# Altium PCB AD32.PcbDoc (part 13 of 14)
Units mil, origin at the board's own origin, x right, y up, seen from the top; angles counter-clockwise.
Board outline 7007.87 x 4368.85 mil, 12 copper layers (Top Layer, Int1 (GND), Int2 (AVDD), Int3 (DVDD), Int4 (GND), Int5 (ST), Int6 (SB), Int8 (AGND), Int7 (AVCC), Int9 (VCCA), Int10 (GND), Bottom Layer), stack 60.136 mil thick; 1350 components, 880 nets, 4712 pads, 2835 vias.
Unrouted connection lines stored in the file: 19.
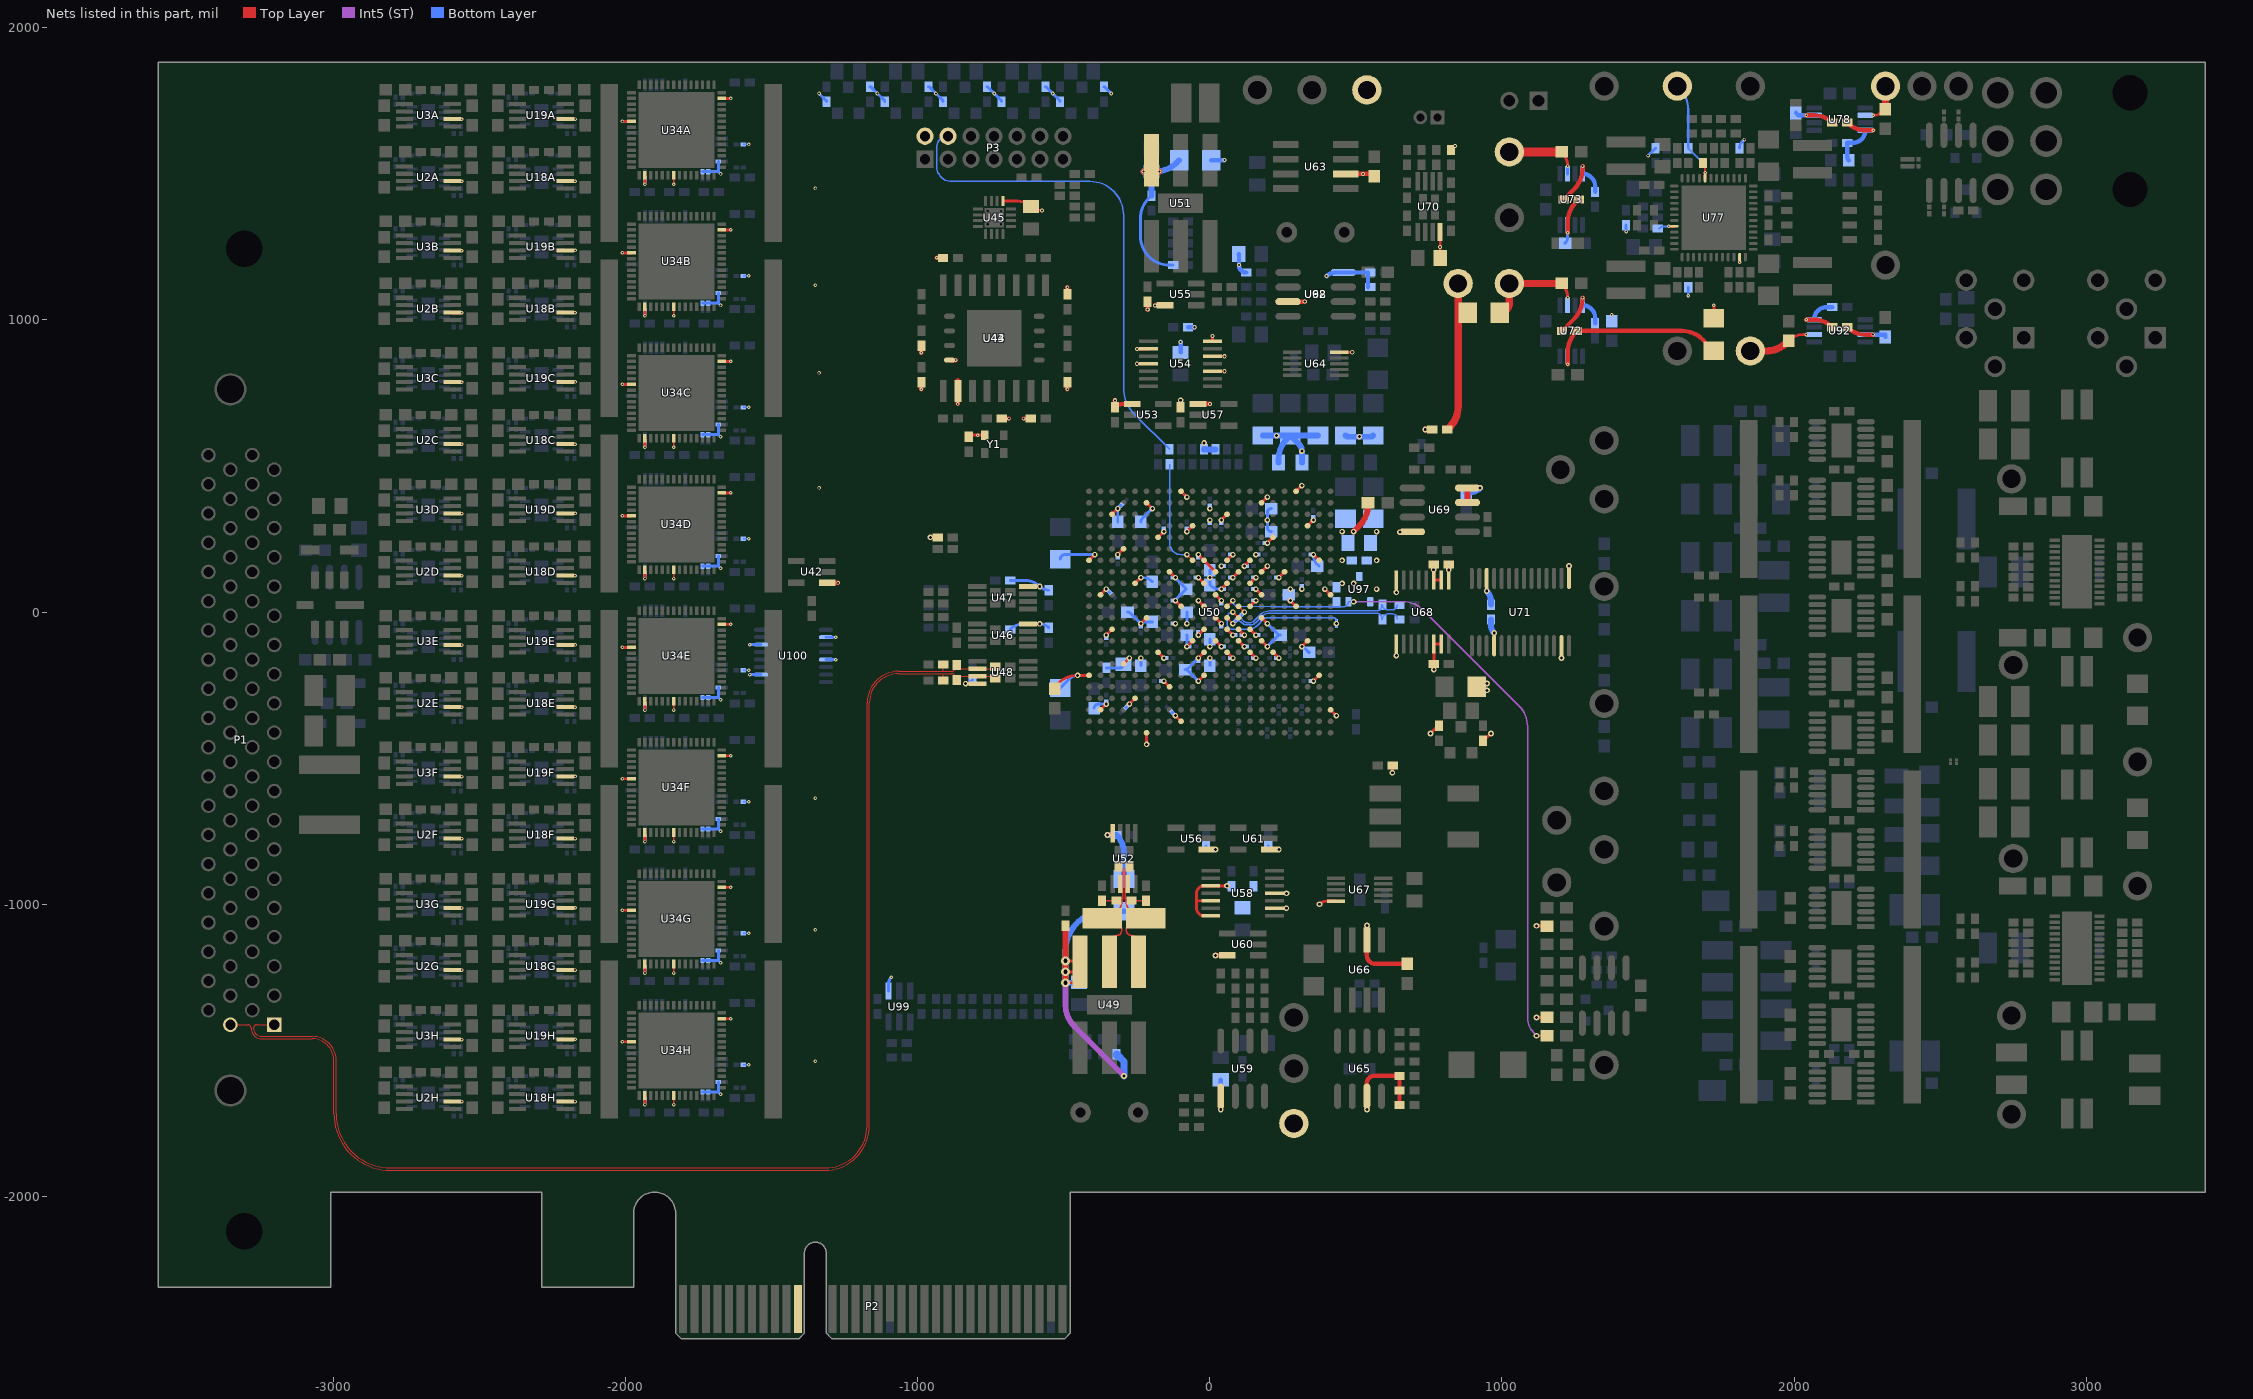
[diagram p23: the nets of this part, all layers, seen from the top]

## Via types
v1: diameter 12, hole 6, Top Layer to Bottom Layer, tented both sides, 1497 vias
v2: diameter 20, hole 10, Top Layer to Bottom Layer, tented both sides, 364 vias
v3: diameter 19, hole 10, Top Layer to Bottom Layer, tented both sides, 347 vias
v4: diameter 14, hole 7, Top Layer to Bottom Layer, tented both sides, 228 vias
v5: diameter 19.68, hole 7.87, Top Layer to Bottom Layer, 225 vias
v6: diameter 19.02, hole 10, Top Layer to Bottom Layer, tented both sides, 85 vias
v7: diameter 20, hole 10, Top Layer to Bottom Layer, 32 vias
v8: diameter 40, hole 20, Top Layer to Bottom Layer, tented both sides, 14 vias
v9: diameter 30, hole 15, Top Layer to Bottom Layer, tented both sides, 12 vias
v10: diameter 25, hole 13, Top Layer to Bottom Layer, 8 vias
v11: diameter 40, hole 20, Top Layer to Bottom Layer, 6 vias
v12: diameter 50, hole 20, Top Layer to Bottom Layer, 6 vias
v13: diameter 66, hole 47, Top Layer to Bottom Layer, tented both sides, 3 vias
v14: diameter 63, hole 45, Top Layer to Bottom Layer, 2 vias
v15: diameter 50, hole 25, Top Layer to Bottom Layer, 2 vias
v16: diameter 12, hole 6, Top Layer to Bottom Layer, 2 vias
v17: diameter 60, hole 40, Top Layer to Bottom Layer, tented both sides, 1 vias
v18: diameter 60, hole 40, Top Layer to Bottom Layer, 1 vias

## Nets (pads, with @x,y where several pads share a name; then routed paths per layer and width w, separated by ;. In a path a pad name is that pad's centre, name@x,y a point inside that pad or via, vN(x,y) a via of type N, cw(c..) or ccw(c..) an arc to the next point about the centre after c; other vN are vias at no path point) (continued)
TMS_FPGA: R374.2 U50.T13 | length 379.1
  Top Layer w5: v3(-78.74,196.85) U50.T13@-59.05,177.17
  Bottom Layer w5: R374.2@-137.8,505.91 -137.8,236.12 ccw(c-98.53,236.12) -98.53,196.85 v3(-78.74,196.85)
TMS_JTAG: P3.4 R374.1 | length 1721.3
  Bottom Layer w5: P3.4@-896.26,1628.74 ccw(c-896.26,1590.04) -934.96,1590.04 -934.96,1550 -935.02,1525.62 ccw(c-883.51,1525.62) -883.51,1474.11 -411.02,1474.11 cw(c-411.02,1358.36) -295.28,1358.36 -295.28,769.03 ccw(c-163.78,769.03) -256.76,676.05 R374.1@-137.8,557.09
TRG_N: P1.2 R137.2 R143.1 R148.2 U48.7 | length 4617.4
  Top Layer w4: P1.2@-3352.3,-1412.5 -3293.31,-1412.5 cw(c-3293.31,-1424.5) -3281.3,-1424.5 ccw(c-3245.68,-1424.5) -3245.68,-1460.12 -3072.5,-1460.12 cw(c-3072.5,-1534.62) -2998,-1534.62 -2998,-1717.62 ccw(c-2805.12,-1717.62) -2805.12,-1910.5 -1317.5,-1910.5 ccw(c-1317.5,-1758) -1165,-1758 -1165,-310.69 cw(c-1065,-310.69) -1065,-210.69 -911.91,-210.69 ; R137.2@-911.91,-233.9 -911.91,-210.69 ; R143.1@-873.13,-219.49 U48.7@-795.08,-219.49 -750.89,-219.49 cw(c-750.89,-243.01) R148.2@-734.25,-226.38 ; R143.1@-866.14,-232.28 cw(c-860.11,-226.25) -868.64,-226.25 ccw(c-884.2,-226.25) -870.19,-219.49 ccw(c-884.2,-226.25) -884.2,-210.69 -911.91,-210.69
TRG_P: P1.1 R136.1 R143.2 R149.2 U48.6 | length 4609.6
  Top Layer w4: P1.1@-3202.3,-1412.5 -3261.3,-1412.5 ccw(c-3261.3,-1424.5) -3273.3,-1424.5 ccw(c-3245.68,-1424.5) -3245.68,-1452.12 -3072.5,-1452.12 cw(c-3072.5,-1534.62) -2990,-1534.62 -2990,-1717.62 ccw(c-2805.12,-1717.62) -2805.12,-1902.5 -1317.5,-1902.5 ccw(c-1317.5,-1758) -1173,-1758 -1173,-310.69 cw(c-1065,-310.69) -1065,-202.69 -911.91,-202.69 ; R136.1@-911.91,-178.9 -911.91,-202.69 ; R143.2@-877.26,-193.9 U48.6@-795.08,-193.9 -750.89,-193.9 ccw(c-750.89,-170.37) R149.2@-734.25,-187.01 ; R143.2@-866.14,-181.1 ccw(c-860.11,-187.14) -868.64,-187.14 cw(c-884.2,-187.14) -870.19,-193.9 cw(c-884.2,-187.14) -884.2,-202.69 -911.91,-202.69
VCC: C40.2 C41.2 C42.2 C55.2 C116.1 C117.1 C143.1 C187.2 C201.2 C203.1 C216.2 C229.2 C236.2 C241.1 C256.2 C274.2 C275.2 C282.2 FR3.1 FR11.2 FR12.2 R194.1 R197.1 R209.1 R210.1 R240.1 R267.1 R345.2 R385.1 R387.1 TP10.1 U46.8 U47.8 U48.8 U52.8 U53.1 U54.2 U54.4 U54.10 U54.12 U54.14 U55.5 U56.1 U57.1 U58.2 U58.4 U58.10 U58.12 U58.14 U60.5 U61.1 U70.8 U72.2 U73.7 U78.7 U92.7 | length 2687.5
  Top Layer w8: C55.2@783.46,1218.75 ccw(c783.46,1223.67) 788.39,1223.67 U70.8@788.39,1301.08
  Top Layer w9.92: U58.14@3.25,-1039.27 -19.72,-1039.27 cw(c-19.72,-1013.68) -45.31,-1013.68 -45.31,-988.09 ; U58.12@3.25,-988.09 -45.31,-988.09 ; v2(58.78,-936.91) U58.10@3.25,-936.91 -19.72,-936.91 ccw(c-19.72,-962.5) -45.31,-962.5 -45.31,-988.09
  Top Layer w10: v3(-835.96,-245.08) U48.8@-795.08,-245.08 ; U46.8@-622.24,-40.35 v3(-582.07,-40.35) ; U47.8@-622.24,87.6 v3(-582.07,87.6) ; v4(-249.61,850) U54.4@-209.25,850 ; v4(-249.61,901.18) U54.2@-209.25,901.18 ; U56.1@-9.35,-812.4 -9.25,-812.5 v2(19.69,-812.5) ; U54.10@9.25,824.41 v4(50,824.41) ; U54.12@9.25,875.59 v4(50,875.59) ; U54.14@9.25,926.77 v4(9.25,945.37) ; U61.1@203.15,-812.4 203.25,-812.5 v2(236.22,-812.5) ; U58.2@221.75,-1013.68 221.85,-1013.78 v2(261.81,-1013.78) ; U58.4@221.75,-962.5 v2(261.91,-962.5) ; R194.1@825,1581.84 838.66,1595.5 v4(838.66,1595.58) ; R210.1@1204.04,1125 1205.15,1123.89 cw(c1157.93,1076.67) v1(1224.7,1076.67)
  Top Layer w15: v2(-350,-762.5) -337.3,-762.5 ccw(c-337.3,-757.33) U52.8@-332.14,-757.33 ; v4(-325,725) C40.2@-325,700.59 cw(c-296.49,672.08) -296.49,712.4 U53.1@-265.65,712.4 U53.1@-265.55,712.5 ; v4(-212.5,1035) C41.2@-212.5,1061.91 ; v4(-187.5,1050) -153.15,1050 U55.5@-153.15,1050.1 ; C42.2@-100,700.59 v6(-100,725) ; U57.1@-40.65,712.4 -40.55,712.5 v4(0,712.5) ; v2(19.69,-1174.9) U60.5@59.35,-1174.9 ; v1(1224.7,1298.33) 1224.7,1332.69 cw(c1324.7,1332.69) 1253.99,1403.4 C143.1@1263.09,1412.5 ; v1(2042.08,1700.3) 2069.59,1700.3 cw(c2069.59,1613.93) C117.1@2130.66,1675 ; C116.1@2181.84,975 ccw(c2242.91,1036.07) 2242.91,949.7 v1(2270.15,949.7)
  Top Layer w25: FR3.1@992.62,1025 ccw(c992.62,1057.38) 1025,1057.38 TP10.1@1025,1125 R210.1@1204.04,1125
  Bottom Layer w9.92: v3(-582.07,87.6) ccw(c-551.18,118.49) C274.2@-551.18,74.8
  Bottom Layer w10: v3(-835.96,-245.08) ccw(c-835.96,-220.04) -818.26,-237.75 C282.2@-812.5,-231.99 ; R385.1@-683.07,-59.06 cw(c-637.92,-104.2) -637.92,-40.35 v3(-582.07,-40.35) cw(c-582.07,-84.04) C275.2@-551.18,-53.15 ; R387.1@-683.07,108.27 -631.97,108.27 cw(c-631.97,37.7) v3(-582.07,87.6) ; C229.2@-12.5,-800.59 ccw(c-0.59,-800.59) -0.59,-812.5 v2(19.69,-812.5) ; C187.2@200,-800.59 ccw(c211.91,-800.59) 211.91,-812.5 v2(236.22,-812.5) ; R209.1@1214.84,1264.19 R209.1@1216.54,1262.5 ccw(c1196.81,1282.22) 1224.7,1282.22 v1(1224.7,1298.33) U73.7@1224.7,1324.9 ; v1(1425,1302.5) R345.2@1425,1324.41
  Bottom Layer w15: C241.1@-100,888.39 v4(-100,925) ; C236.2@-74.41,975 v4(-52.1,975) ; FR11.2@5.12,1546.74 v4(50,1546.74) ; R240.1@2006.25,1708.46 2014.42,1700.3 v1(2042.08,1700.3) U78.7@2068.65,1700.3 ; U92.7@2243.57,949.7 2312.5,949.7 R267.1@2312.5,941.54
  Bottom Layer w20: v2(-350,-762.5) C256.2@-319.34,-762.5 cw(c-381.12,-824.28) -293.75,-824.28 FR12.2@-293.75,-913.63
  other v1: 1375,1017.62
  other v4: 788.39,1250
VCC1V0: C153.2 C160.2 C171.2 C182.2 C183.2 C189.1 C194.1 C195.1 C196.1 C197.1 C198.1 C199.1 C210.1 C211.1 C212.2 C213.2 C214.1 C215.1 C218.1 C219.1 C225.2 C226.2 C227.2 R243.1 R344.2 TP28.1 U50.H8 U50.H10 U50.J7 U50.J9 U50.J11 U50.K8 U50.L7 U50.L11 U50.M8 U50.N7 U50.N11 U50.P8 U50.P10 U50.R7 U50.R9 U50.T8 U50.T10 U92.2 | length 1144.4
  Top Layer w10: U50.J11@19.69,-98.43 v3(39.37,-118.11) ; U50.L11@19.69,-19.68 v3(39.37,-39.37) ; U50.N11@19.69,59.06 v3(39.37,39.37) ; v3(39.37,78.74) U50.P10@59.06,98.43 ; U50.H10@59.06,-137.8 v3(78.74,-157.48) ; U50.T10@59.06,177.17 v3(78.74,196.85) ; v3(78.74,118.11) U50.R9@98.43,137.8 ; U50.J9@98.43,-98.43 v3(118.11,-118.11) ; v3(118.11,157.48) U50.T8@137.8,177.17 ; U50.H8@137.8,-137.8 v3(157.48,-157.48) ; U50.K8@137.8,-59.06 v3(157.48,-78.74) ; U50.M8@137.8,19.69 v3(157.48,39.37) ; U50.P8@137.8,98.43 v3(157.48,118.11) ; v3(157.48,78.74) U50.N7@177.17,59.06 ; U50.J7@177.17,-98.43 v3(196.85,-118.11) ; U50.L7@177.17,-19.68 v3(196.85,-39.37) ; U50.R7@177.17,137.8 v3(196.85,157.48) ; R243.1@1981.25,929.04 cw(c2031.15,879.14) 2031.15,949.7 v1(2041.8,949.7)
  Top Layer w25: TP28.1@1850,893.75 1904.54,893.75 ccw(c1904.54,993.75) 1975.25,923.04 R243.1@1981.25,929.04
  Bottom Layer w10: v3(0,-118.11) C225.2@0,-92.52 ; C227.2@0,143.7 v3(0,118.11) C226.2@0,92.52 ccw(c33.26,125.78) 33.26,78.74 v3(39.37,78.74) ; v3(196.85,-118.11) C171.2@236.22,-78.74 ; v3(196.85,-39.37) C171.2@236.22,-78.74 ; C182.2@210.63,275.59 cw(c210.63,289.37) 196.85,289.37 v3(196.85,314.96) 196.85,340.55 cw(c210.63,340.55) C183.2@210.63,354.33 ; C171.2@242.13,-78.74 C171.2@236.22,-78.74 ; v1(1500,1562.5) R344.2@1525,1587.5
  Bottom Layer w20: C160.2@464.57,604.33 ccw(c474.07,613.84) 474.07,600.39 v3(511.81,600.39) 549.55,600.39 ccw(c549.55,613.84) C153.2@559.06,604.33
  other v3: 39.37,157.48
VCC1V8: C37.2 C165.1 C166.2 C174.2 C177.1 C185.2 C220.2 C222.2 C223.2 C224.2 C230.2 C231.2 C232.2 C233.2 C234.2 C235.2 C237.2 C238.2 C239.2 C240.2 C243.2 C244.2 C245.2 C246.2 C247.2 C249.2 C250.2 C251.2 C252.2 C253.2 C254.2 C255.2 C257.2 C259.2 C260.2 C261.2 C262.1 C263.2 C265.2 C266.2 C267.2 C268.2 C269.1 C270.2 C271.2 C272.2 C360A.1 C360B.1 C360C.1 C360D.1 C360E.1 C360F.1 C360G.1 C360H.1 P3.2 R133.2 R134.2 R140.2 R142.1 R145.1 R146.2 R155.1 R158.2 R160.2 R191.2 R260.1 R337.2 R367.2 R369.2 R379.2 R402A.1 R402B.1 R402C.1 R402D.1 R402E.1 R402F.1 R402G.1 R402H.1 R417A.2 R417B.2 R417C.2 R417D.2 R417E.2 R417F.2 R417G.2 R417H.2 R457A.2 R457B.2 R457C.2 R457D.2 R457E.2 R457F.2 R457G.2 R457H.2 R473A.2 R473B.2 R473C.2 R473D.2 R473E.2 R473F.2 R473G.2 R473H.2 TP30.1 U34A.13 U34A.44 U34A.49 U34B.13 U34B.44 U34B.49 U34C.13 U34C.44 U34C.49 U34D.13 U34D.44 U34D.49 U34E.13 U34E.44 U34E.49 U34F.13 U34F.44 U34F.49 U34G.13 U34G.44 U34G.49 U34H.13 U34H.44 U34H.49 U43.2 U44.8 U45.5 U50.A17 U50.AA17 U50.AB14 U50.B14 U50.C21 U50.D18 U50.E15 U50.F12 U50.F22 U50.G19 U50.H12 U50.H16 U50.J13 U50.K12 U50.K20 U50.L17 U50.M12 U50.M14 U50.N21 U50.P12 U50.P18 U50.R11 U50.R15 U50.T12 U50.T22 U50.U19 U50.V16 U50.W13 U50.Y10 U50.Y20 U67.10 U78.2 U99.1 U100.2 U100.5 U100.10 U100.14 Y1.4 | length 5255.7
  Top Layer w5: v1(-1834.84,-1685.43) U34H.49@-1834.84,-1654.62 ; v1(-1834.84,-1235.43) U34G.49@-1834.84,-1204.62 ; v1(-1834.84,-785.43) U34F.49@-1834.84,-754.62 ; v1(-1834.84,-335.43) U34E.49@-1834.84,-304.62 ; v1(-1834.84,114.57) U34D.49@-1834.84,145.38 ; v1(-1834.84,564.57) U34C.49@-1834.84,595.38 ; v1(-1834.84,1014.57) U34B.49@-1834.84,1045.38 ; v1(-1834.84,1464.57) U34A.49@-1834.84,1495.38
  Top Layer w9.65: v3(-354.33,-78.74) U50.K20@-334.65,-59.06
  Top Layer w10: v1(-1933.27,-1685.43) U34H.44@-1933.27,-1654.62 ; v1(-1933.27,-1235.43) U34G.44@-1933.27,-1204.62 ; v1(-1933.27,-785.43) U34F.44@-1933.27,-754.62 ; v1(-1933.27,-335.43) U34E.44@-1933.27,-304.62 ; v1(-1933.27,114.57) U34D.44@-1933.27,145.38 ; v1(-1933.27,564.57) U34C.44@-1933.27,595.38 ; v1(-1933.27,1014.57) U34B.44@-1933.27,1045.38 ; v1(-1933.27,1464.57) U34A.44@-1933.27,1495.38 ; U34H.13@-1670.38,-1391.73 v1(-1639.57,-1391.73) ; U34G.13@-1670.38,-941.73 v1(-1639.57,-941.73) ; U34F.13@-1670.38,-491.73 v1(-1639.57,-491.73) ; U34E.13@-1670.38,-41.73 v1(-1639.57,-41.73) ; U34D.13@-1670.38,408.27 v1(-1639.57,408.27) ; U34C.13@-1670.38,858.27 v1(-1639.57,858.27) ; U34B.13@-1670.38,1308.27 v1(-1639.57,1308.27) ; U34A.13@-1670.38,1758.27 v1(-1639.57,1758.27) ; v3(-956.69,255.91) R140.2@-931.1,255.91 ; R145.1@-825,600.59 cw(c-813.12,588.71) -813.12,605.51 v1(-794.18,605.51) Y1.4@-769.98,605.51 ; U45.5@-707.97,1406.5 -656.22,1406.5 cw(c-656.22,1344.66) C37.2@-612.5,1388.39 ccw(c-580.18,1420.7) -580.18,1375 v4(-575,1375) ; C249.2@-531.5,-255.91 -519.96,-244.37 cw(c-452.76,-311.58) v3(-452.76,-216.54) U50.F22@-413.39,-216.54 ; U50.T22@-413.39,177.17 v3(-393.7,196.85) ; U50.C21@-374.02,-334.65 v3(-354.33,-314.96) ; U50.N21@-374.02,59.06 v3(-354.33,78.74) ; U50.Y20@-334.65,334.65 v3(-314.96,354.33) ; v3(-314.96,196.85) U50.U19@-295.28,216.54 ; U50.G19@-295.28,-177.17 v3(-275.59,-157.48) ; v3(-275.59,-314.96) U50.D18@-255.91,-295.28 ; U50.P18@-255.91,98.43 v3(-236.22,118.11) ; v3(-236.22,-39.37) U50.L17@-216.54,-19.68 ; v3(-216.54,-452.76) U50.A17@-216.54,-413.39 ; U50.AA17@-216.54,374.02 v3(-196.85,354.33) ; U50.H16@-177.17,-137.8 v3(-157.48,-157.48) ; U50.V16@-177.17,255.91 v3(-157.48,275.59) ; v3(-157.48,-236.22) U50.E15@-137.8,-255.91 ; U50.R15@-137.8,137.8 v3(-118.11,118.11) ; v3(-118.11,-354.33) U50.B14@-98.43,-374.02 ; v3(-118.11,39.37) U50.M14@-98.43,19.69 ; U50.AB14@-98.43,413.39 v3(-78.74,393.7) ; v3(-78.74,-118.11) U50.J13@-59.05,-98.43 ; v3(-78.74,275.59) U50.W13@-59.05,295.28 ; v3(-39.37,-236.22) U50.F12@-19.68,-216.54 ; v3(-39.37,-157.48) U50.H12@-19.68,-137.8 ; v3@-39.37,-78.74 U50.K12@-19.68,-59.06 ; v3(-39.37,39.37) U50.M12@-19.68,19.69 ; v3(-39.37,118.11) U50.P12@-19.68,98.43 ; v3(-39.37,196.85) U50.T12@-19.68,177.17 U50.R11@19.69,137.8 ; v3(39.37,314.96) U50.Y10@59.06,334.65 ; v2(375,-1000) cw(c400.66,-1025.66) 400.66,-989.37 U67.10@431.79,-989.37 ; v3(625,-550) 625,-525.59 R379.2@625.59,-525 ; v2(755,-415) 777.47,-392.53 cw(c785,-400.05) R191.2@785,-389.41 ; v1(2270.42,1700.3) ccw(c2270.42,1751.98) 2306.97,1715.43 R260.1@2312.5,1720.96
  Top Layer w15: v1@-987.5,763.09 R133.2@-987.5,786.91 ; v1(-987.5,887.5) R134.2@-987.5,911.91 ; v1(-934.96,1212.5) R142.1@-913.09,1212.5 ; U44.8@-891.04,862.5 v1(-869.9,862.5) ; v1(-862.5,712.5) U43.2@-862.5,756.4 U43.2@-862.5,793.59 ; R146.2@-711.91,662.5 v1(-687.5,662.5) ; v1(-637.5,662.5) R155.1@-613.09,662.5 ; v1(-487.5,763.09) R158.2@-487.5,786.91 ; R160.2@-487.5,1088.09 v1(-487.5,1111.91)
  Top Layer w25: R260.1@2312.5,1720.96 TP30.1@2312.5,1800
  Bottom Layer w5: R402H.1@-1596.82,-1549.21 v1(-1577.95,-1549.21) ; R402G.1@-1596.82,-1099.21 v1(-1577.95,-1099.21) ; R402F.1@-1596.82,-649.21 v1(-1577.95,-649.21) ; R402E.1@-1596.82,-199.21 v1(-1577.95,-199.21) ; R402D.1@-1596.82,250.79 v1(-1577.95,250.79) ; R402C.1@-1596.82,700.79 v1(-1577.95,700.79) ; R402B.1@-1596.82,1150.79 v1(-1577.95,1150.79) ; R402A.1@-1596.82,1600.79 v1(-1577.95,1600.79) ; C268.2@-358.97,-80.01 C268.2@-354.33,-86.44
  Bottom Layer w10: v1(-1933.27,-1685.43) C360H.1@-1933.27,-1666.56 ; v1(-1933.27,-1235.43) C360G.1@-1933.27,-1216.56 ; v1(-1933.27,-785.43) C360F.1@-1933.27,-766.56 ; v1(-1933.27,-335.43) C360E.1@-1933.27,-316.56 ; v1(-1933.27,114.57) C360D.1@-1933.27,133.44 ; v1(-1933.27,564.57) C360C.1@-1933.27,583.44 ; v1(-1933.27,1014.57) C360B.1@-1933.27,1033.44 ; v1(-1933.27,1464.57) C360A.1@-1933.27,1483.44 ; R473H.2@-1736.42,-1642.69 R457H.2@-1716.73,-1642.69 -1682.31,-1642.69 ; R473G.2@-1736.42,-1192.69 R457G.2@-1716.73,-1192.69 -1682.31,-1192.69 ; R473F.2@-1736.42,-742.69 R457F.2@-1716.73,-742.69 -1682.31,-742.69 ; R473E.2@-1736.42,-292.69 R457E.2@-1716.73,-292.69 -1682.31,-292.69 ; R473D.2@-1736.42,157.31 R457D.2@-1716.73,157.31 -1682.31,157.31 ; R473C.2@-1736.42,607.31 R457C.2@-1716.73,607.31 -1682.31,607.31 ; R473B.2@-1736.42,1057.31 R457B.2@-1716.73,1057.31 -1682.31,1057.31 ; R473A.2@-1736.42,1507.31 R457A.2@-1716.73,1507.31 -1682.31,1507.31 ; R417H.2@-1682.31,-1608.27 -1682.31,-1642.69 ; R417G.2@-1682.31,-1158.27 -1682.31,-1192.69 ; R417F.2@-1682.31,-708.27 -1682.31,-742.69 ; R417E.2@-1682.31,-258.27 -1682.31,-292.69 ; R417D.2@-1682.31,191.73 -1682.31,157.31 ; R417C.2@-1682.31,641.73 -1682.31,607.31 ; R417B.2@-1682.31,1091.73 -1682.31,1057.31 ; R417A.2@-1682.31,1541.73 -1682.31,1507.31 ; v1(-1674.74,-1650.26) -1682.31,-1642.69 ; v1(-1674.74,-1200.26) -1682.31,-1192.69 ; v1(-1674.74,-750.26) -1682.31,-742.69 ; v1(-1674.74,-300.26) -1682.31,-292.69 ; v1(-1674.74,149.74) -1682.31,157.31 ; v1(-1674.74,599.74) -1682.31,607.31 ; v1(-1674.74,1049.74) -1682.31,1057.31 ; v1(-1674.74,1499.74) -1682.31,1507.31 ; v1(-1574.41,-213.98) U100.10@-1536.22,-213.98 ; v1(-1574.41,-111.35) U100.14@-1536.22,-111.61 ; U100.5@-1313.78,-162.8 v1(-1280,-162.8) ; U100.2@-1313.78,-86.02 v1(-1280,-86.02) ; U99.1@-1100,-1296.85 U99.1@-1099.9,-1296.85 -1099.9,-1273.9 cw(c-1066.1,-1273.9) v1(-1090,-1250) ; C271.2@-511.81,-259.84 -479.64,-227.67 cw(c-452.76,-254.55) v3(-452.76,-216.54) ; C272.2@-511.82,181.1 cw(c-496.06,181.1) -496.06,196.85 v3(-393.7,196.85) ; C270.2@-395.67,-328.74 cw(c-381.89,-328.74) -381.89,-314.96 v3(-354.33,-314.96) ; C269.1@-354.33,-190.94 -308.07,-190.94 ccw(c-308.07,-178.15) C262.1@-295.28,-178.15 ; v3(-354.33,78.74) C266.2@-343.12,67.53 ; C265.2@-314.96,309.06 v3(-314.96,354.33) C260.2@-303.75,365.54 ; C261.2@-286.8,-326.17 v3(-275.59,-314.96) ; C259.2@-281.5,0 cw(c-281.5,-14.26) -271.41,-4.18 v3(-236.22,-39.37) ; C254.2@-236.22,-183.07 v3(-236.22,-157.48) ; C253.2@-236.22,-47.07 -236.22,-43.14 v3(-236.22,-39.37) ; v3(-236.22,118.11) -230.12,118.11 cw(c-230.12,71.06) C252.2@-196.85,104.33 ; C255.2@-236.22,309.06 cw(c-221.96,309.06) -232.04,319.14 v3(-196.85,354.33) ; C251.2@-196.85,-33.46 -221.96,-33.46 ccw(c-221.96,-53.63) v3(-236.22,-39.37) ; C257.2@-129.32,-343.12 v3(-118.11,-354.33) ; v3(-118.11,-39.37) ccw(c-113.36,-39.37) v3@-116.72,-42.73 ; v3(-118.11,39.37) cw(c-113.36,39.37) -116.73,42.72 C239.2@-80.71,78.74 -116.72,114.75 cw(c-113.36,118.11) v3(-118.11,118.11) ; v3(-78.74,-118.11) C237.2@-78.74,-78.74 ; v3(-78.74,-39.37) C238.2@-78.74,0 ; v3(-39.37,-236.22) -74.56,-201.03 ccw(c-84.65,-211.11) C240.2@-84.65,-196.85 ccw(c-84.65,-182.59) -74.56,-192.67 v3(-39.37,-157.48) ; R369.2@-19.69,557.09 v3(-19.68,578.74) ; C224.2@0,-183.07 v3(0,-157.48) ; v1(1637.5,1082.5) R337.2@1637.5,1111.91
  Bottom Layer w20: R369.2@-19.69,557.09 R367.2@19.69,557.09 ; C185.2@181.1,604.33 v3(228.52,604.33) C174.2@275.59,604.33 ; C177.1@235.24,511.81 235.24,522.56 cw(c335.24,522.56) 264.53,593.27 C174.2@275.59,604.33 ; C165.1@315.94,511.81 315.94,548.8 ccw(c312.58,548.8) v3(314.96,551.18) ccw(c281.69,551.18) 305.22,574.7 C174.2@275.59,604.33 ; C166.2@370.08,604.33 C174.2@275.59,604.33
  other v1: -1350,-1537.5 -1350,-1087.5 -1350,-637.5 -1337.5,425 -987.5,762.5 -1337.5,818.75 -1350,1118.75 -1350,1450
  other v3: -39.37,-78.61 0,314.96 0,354.33
VCC2: C57.1 C59.2 C144.1 FR3.2 TP9.1 U68.1 U69.8 U71.1 U71.18 | length 731.4
  Top Layer w10: U68.1@817.91,109.25 C59.2@817.91,162.5 ; 850,1025 FR3.2@882.38,1025 ; U71.18@973.43,-115.16 v2(973.43,-72.05) ; U71.1@1229.33,115.16 v2(1229.33,157.48)
  Top Layer w25: C57.1@813.09,625 820.71,632.62 ccw(c750,703.33) 850,703.33 850,1025 TP9.1@850,1125
  Bottom Layer w20: C144.1@962.5,-25.59 962.5,-45.67 ccw(c999.8,-45.67) v2(973.43,-72.05)
  other v3: 817.8,144.34 650.49,273.5
VCC2V5: C140.2 C164.2 C167.2 C168.2 C169.2 C170.2 C173.2 C176.2 C179.2 C180.2 C190.2 C191.2 FR2.2 R195.1 R211.1 R378.2 R380.1 R381.2 R388.1 R389.2 R393.1 R394.2 R398.1 R399.2 R400.1 TP12.1 U42.1 U50.AA7 U50.AB4 U50.C1 U50.F2 U50.H6 U50.J3 U50.M4 U50.N1 U50.R5 U50.T2 U50.V6 U50.W3 U64.10 U73.2 U77.8 | length 1309.7
  Top Layer w10: U50.AA7@177.17,374.02 v3(196.85,393.7) ; v3(196.85,236.22) U50.V6@216.54,255.91 ; U50.H6@216.54,-137.8 v3(236.22,-157.48) ; v3(236.22,118.11) U50.R5@255.91,137.8 ; v3(275.59,39.37) U50.M4@295.28,19.69 ; U50.AB4@295.28,413.39 v3(314.96,433.07) ; v3(314.96,-118.11) U50.J3@334.65,-98.43 ; U50.W3@334.65,295.28 v3(354.33,314.96) ; v3(354.33,-236.22) U50.F2@374.02,-216.54 ; v3(354.33,196.85) U50.T2@374.02,177.17 ; v3(393.7,78.74) U50.N1@413.39,59.06 ; U50.C1@413.39,-334.65 v3(433.07,-354.33) ; U64.10@443.21,889.37 v4(487.5,889.37) ; R195.1@935,-440.59 ccw(c935,-435.98) 938.26,-439.24 v2(962.5,-415) ; v2(948.82,-267.72) 941.9,-267.72 cw(c941.9,-227.39) FR2.2@913.39,-255.91 cw(c941.9,-284.42) 941.9,-244.09 v2(948.82,-244.09) ; R211.1@1206,1575 R211.1@1204.04,1575 1205.15,1573.89 cw(c1157.93,1526.67) v1@1224.7,1527.21 ; v1(1571,1320.47) U77.8@1590.16,1320.47 ; v1@1224.7,1527.21 cw(c1157.93,1526.67) v1(1224.7,1526.67) v1@1224.7,1527.21
  Top Layer w15: U42.1@-1309.35,100.1 -1272.6,100.1 v1(-1272.5,100)
  Top Layer w30: TP12.1@1006.25,1575 TP12.1@1025,1575 R211.1@1204.04,1575
  Bottom Layer w7: C140.2@1538.09,1312.5 cw(c1557.34,1293.25) 1557.34,1320.47 v1(1571,1320.47)
  Bottom Layer w10: v1(-1337.5,1775) -1312.5,1750 R400.1@-1312.5,1746.91 ; R399.2@-1162.5,1798.09 -1160.59,1798.09 v1(-1137.5,1775) -1112.5,1750 R398.1@-1112.5,1746.91 ; R394.2@-962.5,1798.09 -960.59,1798.09 v1(-937.5,1775) -912.5,1750 R393.1@-912.5,1746.91 ; R389.2@-762.5,1798.09 -760.59,1798.09 v1(-737.5,1775) -712.5,1750 R388.1@-712.5,1746.91 ; R381.2@-562.5,1798.09 -560.59,1798.09 v1(-537.5,1775) -512.5,1750 R380.1@-512.5,1746.91 ; R378.2@-362.5,1798.09 -360.59,1798.09 v1(-337.5,1775) ; v3(314.96,-118.11) 316.68,-119.83 320.62,-119.83 338.58,-137.8 C164.2@340.55,-137.8 ; v3(354.33,196.85) ccw(c401.85,196.85) 368.25,163.25 C168.2@374.02,157.48 ; U73.2@1224.7,1500.1 v1(1224.7,1526.67)
  other v3: 275.59,78.74 314.96,78.74 157.48,196.85
VCOCLK_N: R162.2 R163.1 R164.2 TP41.1 U49.5 U52.2 | length 524.4
  Top Layer w5: R162.2@-368.75,-988.09 R163.1@-319.34,-988.09 ; U49.5@-343.75,-1196.75 -343.75,-1132.34 cw(c-318.16,-1132.34) -318.16,-1106.75 ccw(c-318.16,-1090.83) -302.24,-1090.83 -302.24,-1082.5 ccw(c-337.24,-1082.5) -337.24,-1047.5 TP41.1@-367.5,-1047.5 ccw(c-367.5,-978.72) -298.72,-978.72 ; R163.1@-319.34,-987.5 R163.1@-319.34,-988.09 ; R164.2@-312.5,-869.34 cw(c-312.5,-883.12) -298.72,-883.12 -298.72,-978.72 ; R163.1@-319.34,-988.09 cw(c-309.97,-988.09) -309.97,-978.72 -298.72,-978.72
VCOCLK_P: R163.2 R166.1 R167.1 TP42.1 U49.4 U52.3 | length 524.4
  Top Layer w5: R166.1@-275,-869.34 ccw(c-275,-883.12) -288.78,-883.12 -288.78,-978.72 ; U49.4@-243.75,-1196.75 -243.75,-1131.16 ccw(c-268.16,-1131.16) -268.16,-1106.75 cw(c-268.16,-1089.48) -285.43,-1089.48 -285.43,-1082.5 cw(c-250.43,-1082.5) -250.43,-1047.5 TP42.1@-220,-1047.5 cw(c-220,-978.72) -288.78,-978.72 ; R167.1@-218.75,-988.09 -218.75,-987.5 R163.2@-268.16,-987.5 ccw(c-276.94,-987.5) -276.94,-978.72 -288.78,-978.72
VCOMA: U2A.2 U3A.2 U18A.2 U19A.2 U34A.34 | length 165
  Top Layer w10: U2A.2@-2593.31,1474.71 -2592.92,1474.32 -2560.38,1474.32 v1(-2560,1474.7) ; U3A.2@-2593.31,1687.08 v1(-2560,1687.08) ; U18A.2@-2205.81,1474.71 v1(-2172.5,1474.71) ; U19A.2@-2205.81,1687.21 -2205.56,1687.45 -2172.36,1687.45 v1(-2172.11,1687.7) ; v1(-2010.43,1679.53) U34A.34@-1979.62,1679.53
VCOMB: U2B.2 U3B.2 U18B.2 U19B.2 U34B.34 | length 164.9
  Top Layer w10: U2B.2@-2593.31,1024.71 -2592.92,1024.32 -2560.38,1024.32 v1(-2560,1024.7) ; U3B.2@-2593.31,1237.08 v1(-2560,1237.08) ; U18B.2@-2205.81,1024.71 v1(-2172.5,1024.71) ; U19B.2@-2205.81,1237.21 cw(c-2204.6,1236) -2204.6,1237.7 v1(-2172.11,1237.7) ; v1(-2010.43,1229.53) U34B.34@-1979.62,1229.53
VCOMC: U2C.2 U3C.2 U18C.2 U19C.2 U34C.34 | length 165
  Top Layer w10: U2C.2@-2593.31,574.71 -2592.92,574.32 -2560.38,574.32 v1(-2560,574.7) ; U3C.2@-2593.31,787.08 v1(-2560,787.08) ; U18C.2@-2205.81,574.71 v1(-2172.5,574.71) ; U19C.2@-2205.81,787.21 -2205.56,787.45 -2172.36,787.45 v1(-2172.11,787.7) ; v1(-2010.43,779.53) U34C.34@-1979.62,779.53
VCOMD: U2D.2 U3D.2 U18D.2 U19D.2 U34D.34 | length 165
  Top Layer w10: U2D.2@-2593.31,124.71 -2592.92,124.32 -2560.38,124.32 v1(-2560,124.7) ; U3D.2@-2593.31,337.08 v1(-2560,337.08) ; U18D.2@-2205.81,124.71 v1(-2172.5,124.71) ; U19D.2@-2205.81,337.21 -2205.56,337.45 -2172.36,337.45 v1(-2172.11,337.7) ; v1(-2010.43,329.53) U34D.34@-1979.62,329.53
VCOME: U2E.2 U3E.2 U18E.2 U19E.2 U34E.34 | length 164.9
  Top Layer w10: U2E.2@-2593.31,-325.29 -2592.92,-325.68 -2560.38,-325.68 v1(-2560,-325.3) ; U3E.2@-2593.31,-112.92 v1(-2560,-112.92) ; U18E.2@-2205.81,-325.29 v1(-2172.5,-325.29) ; U19E.2@-2205.81,-112.79 cw(c-2204.6,-114) -2204.6,-112.3 v1(-2172.11,-112.3) ; v1(-2010.43,-120.47) U34E.34@-1979.62,-120.47
VCOMF: U2F.2 U3F.2 U18F.2 U19F.2 U34F.34 | length 165
  Top Layer w10: U2F.2@-2593.31,-775.29 -2592.92,-775.68 -2560.38,-775.68 v1(-2560,-775.3) ; U3F.2@-2593.31,-562.92 v1(-2560,-562.92) ; U18F.2@-2205.81,-775.29 v1(-2172.5,-775.29) ; U19F.2@-2205.81,-562.79 -2205.56,-562.54 -2172.36,-562.54 v1(-2172.11,-562.3) ; v1(-2010.43,-570.47) U34F.34@-1979.62,-570.47
VCOMG: U2G.2 U3G.2 U18G.2 U19G.2 U34G.34 | length 164.9
  Top Layer w10: U2G.2@-2593.31,-1225.29 -2592.92,-1225.68 -2560.38,-1225.68 v1(-2560,-1225.3) ; U3G.2@-2593.31,-1012.92 v1(-2560,-1012.92) ; U18G.2@-2205.81,-1225.29 v1(-2172.5,-1225.29) ; U19G.2@-2205.81,-1012.79 cw(c-2204.6,-1014) -2204.6,-1012.3 v1(-2172.11,-1012.3) ; v1(-2010.43,-1020.47) U34G.34@-1979.62,-1020.47
VCOMH: U2H.2 U3H.2 U18H.2 U19H.2 U34H.34 | length 164.9
  Top Layer w10: U2H.2@-2593.31,-1675.29 -2592.92,-1675.68 -2560.38,-1675.68 v1(-2560,-1675.3) ; U3H.2@-2593.31,-1462.92 v1(-2560,-1462.92) ; U18H.2@-2205.81,-1675.29 v1(-2172.5,-1675.29) ; U19H.2@-2205.81,-1462.79 cw(c-2204.6,-1464) -2204.6,-1462.3 v1(-2172.11,-1462.3) ; v1(-2010.43,-1470.47) U34H.34@-1979.62,-1470.47
VREF-PH: C50.2 C51.2 C53.2 C221.1 R180.2 TP4.1 U59.5 U65.3 U66.6 | length 719.9
  Top Layer w15: v2(37.5,-1702.5) U59.5@37.5,-1656.99 ; v2(537.5,-1702.5) U65.3@537.5,-1656.99 537.5,-1612.5 cw(c562.5,-1612.5) 562.5,-1587.5 C51.2@649.41,-1587.5 C50.2@649.41,-1637.5 R180.2@649.41,-1687.5 ; v2(537.5,-1072.5) U66.6@537.5,-1122.64 537.5,-1175 ccw(c566.54,-1175) 566.54,-1204.04 C53.2@675,-1204.04
  Bottom Layer w15: v2(37.5,-1702.5) C221.1@37.5,-1600.89
VREF-PH2: C49.2 C149.2 C150.2 C192.1 R363.2 TP8.1 U62.3 U63.6 U98.5 | length 431.3
  Top Layer w15: U62.3@268.01,1062.5 v4(325,1062.5) ; U63.6@464.86,1500 v4(525,1500) 554.04,1500 cw(c554.04,1491.54) C49.2@562.5,1491.54
  Bottom Layer w15: C192.1@99.11,1225 cw(c99.11,1224.11) 100,1224.11 v4(100,1187.5) 100,1186.91 ccw(c124.41,1186.91) R363.2@124.41,1162.5 ; v4(400,1150) cw(c430.18,1119.82) 430.18,1162.5 U98.5@456.99,1162.5 541.54,1162.5 C149.2@541.54,1112.5
VREG: C72.1 FR4.1 R328.2 R335.2 R338.2 TP26.1 U77.23 U77.44 | length 489.9
  Top Layer w7: C72.1@1687.5,1536.91 cw(c1668.25,1517.66) 1695.47,1517.66 v1(1695.47,1504.04)
  Top Layer w10: U77.44@1695.47,1484.84 v1(1695.47,1504.04) ; FR4.1@1725,1005.12 v1(1725,1050.1) ; v1(1813.58,1197.36) U77.23@1813.58,1215.16
  Bottom Layer w7: TP26.1@1600,1800 1608.21,1791.79 cw(c1537.5,1721.08) 1637.5,1721.08 R338.2@1637.5,1590 ; R338.2@1637.5,1588.09 R338.2@1637.5,1590 ; v1(1695.47,1504.04) 1695.47,1536.91 R335.2@1687.5,1536.91 ccw(c1686.07,1536.91) 1687.08,1537.92 1639.27,1585.73 cw(c1643.54,1590) R338.2@1637.5,1590
  Bottom Layer w10: R328.2@1812.5,1588.09 cw(c1841.25,1588.09) 1820.92,1608.42 v1(1830,1617.5)
VREG2: C142.1 FR4.2 U72.7 | length 615
  Top Layer w15: v1(1224.7,848.33) 1224.7,888.94 cw(c1324.7,888.94) 1253.99,959.65 C142.1@1256.84,962.5 1615.96,962.5 cw(c1615.96,862.5) 1686.67,933.21 FR4.2@1725,894.88
VVCO: C39.2 C258.2 FR12.1 R161.1 U49.6 | length 1412.7
  Top Layer w10: v9(-493.75,-1268.75) U49.6@-443.75,-1268.75 ; v9(-493.75,-1231.25) U49.6@-443.75,-1231.25 ; v9(-493.75,-1193.75) U49.6@-450.99,-1193.75
  Top Layer w20: v9(-493.75,-1268.75) v9(-493.75,-1231.25) v9(-493.75,-1193.75) C39.2@-493.75,-1073.09
  Top Layer w30: U49.6@-450.99,-1193.75 cw(c-450.99,-1203.99) U49.6@-443.75,-1196.75 -443.75,-1231.25 U49.6@-443.75,-1268.75
  Int5 (ST) w20: v9(-493.75,-1193.75) v9(-493.75,-1231.25) v9(-493.75,-1268.75) -493.75,-1346.08 ccw(c-393.75,-1346.08) -464.46,-1416.79 v2(-293.75,-1587.5)
  Bottom Layer w20: C258.2@-447.5,-1266.61 -447.5,-1268.75 v9(-493.75,-1268.75) v9(-493.75,-1231.25) v9(-493.75,-1193.75) -493.75,-1159.94 cw(c-357.68,-1159.94) -357.68,-1023.87 FR12.1@-293.75,-1023.87
  Bottom Layer w25: R161.1@-318.75,-1513.09 -318.75,-1517.03 -317.47,-1518.31 -313.53,-1518.31 -293.75,-1538.09 v2(-293.75,-1587.5)
VVCO2: C228.2 C242.2 FR11.1 R370.2 U51.6 | length 641.2
  Top Layer w20: v4(-227.56,1508.35) U51.6@-200,1508.35 ; U51.6@-200,1546.74 U51.6@-200,1508.35 ; v4(-172.44,1508.35) U51.6@-200,1508.35
  Bottom Layer w10: C228.2@-200,1425.59 -208.27,1417.32 ccw(c-137.56,1346.61) -237.56,1346.61 -237.56,1287.5 ccw(c-137.56,1287.5) -137.56,1187.5 R370.2@-125.59,1187.5
  Bottom Layer w20: v4(-227.56,1508.35) C242.2@-200,1508.35 ; C228.2@-200,1425.59 C242.2@-200,1508.35 ; v4(-172.44,1508.35) C242.2@-184.93,1508.35 ; FR11.1@-105.12,1546.74 -114.21,1537.64 cw(c-184.93,1608.35) C242.2@-184.93,1508.35 ; C242.2@-200,1508.35 C242.2@-184.93,1508.35
WAKE#: P2.B11
XADC_N: C151.2 C204.1 R354.2 U50.M9 | length 641
  Top Layer w5: U50.M9@98.43,19.69 v3(118.11,0)
  Bottom Layer w5: C204.1@106.9,-11.21 v3(118.11,0) ; C204.1@107.61,-10.5 107.61,-14.03 ccw(c129.78,-14.03) 114.1,-29.71 114.69,-30.29 ccw(c128.35,-16.63) 128.35,-35.95 137.8,-35.95 ccw(c137.8,-16.47) 151.57,-30.24 172.5,-9.31 cw(c204.64,-41.45) 204.64,4 572.5,4 ccw(c572.5,19.56) 588.05,19.56 cw(c596.59,19.56) C151.2@590.55,25.59 ccw(c608.64,25.59) 608.64,7.5 624.04,7.5 ccw(c624.04,25) R354.2@641.54,25
XADC_P: C151.1 C204.2 R353.2 U50.L10 | length 649.3
  Top Layer w5: U50.L10@59.06,-19.68 v3(78.74,-39.37)
  Bottom Layer w5: v3(78.74,-39.37) C204.2@89.24,-28.87 ; C204.2@89.95,-28.16 C204.2@89.24,-28.87 ; R353.2@641.54,-25 641.54,-23.74 ccw(c624.04,-23.74) 624.04,-6.24 609.9,-6.24 ccw(c609.9,-25.59) C151.1@590.55,-25.59 cw(c596.59,-19.55) 588.05,-19.55 ccw(c572.5,-19.55) 572.5,-4 204.64,-4 ccw(c204.64,-41.45) 178.16,-14.97 157.23,-35.9 cw(c137.8,-16.47) 137.8,-43.95 128.35,-43.95 cw(c128.35,-16.63) 109.04,-35.96 108.45,-35.36 ccw(c92.77,-51.04) 92.77,-28.87 C204.2@89.24,-28.87
XADC_REF_N: U50.L9 W3.2 | length 482.4
  Top Layer w5: v3(78.74,0) U50.L9@98.43,-19.68
  Bottom Layer w5: v3(78.74,0) ccw(c78.74,-19.68) 59.06,-19.68 59.06,-39.37 ccw(c78.74,-39.37) 78.74,-59.06 129.64,-59.06 ccw(c129.88,-11.44) 163.55,-45.11 183.41,-25.25 cw(c196.85,-38.69) 196.85,-19.68 423.88,-19.68 cw(c423.88,-28.87) W3.2@433.07,-28.87
XADC_REF_P: C163.1 R204.1 U50.M10 U97.2 | length 2351.5
  Top Layer w5: U50.M10@59.06,19.69 v3(78.74,39.37) ; v2(1118.75,-1450) R204.1@1151.54,-1450
  Int5 (ST) w5: v3(492.13,35.43) 660.65,35.43 cw(c660.65,-64.57) 731.36,6.14 1058.21,-320.71 cw(c987.5,-391.42) 1087.5,-391.42 1087.5,-1389.64 ccw(c1157.77,-1389.64) 1108.08,-1439.33 v2(1118.75,-1450)
  Bottom Layer w5: v3(78.74,39.37) ccw(c98.43,39.37) 98.43,19.69 cw(c98.43,14.68) 98.49,19.68 216.46,18.12 457.1,18.12 ccw(c457.1,35.43) U97.2@474.41,35.43 v3(492.13,35.43)
XADCGND: C57.2 C58.1 C59.1 C116.2 C117.2 C142.2 C143.2 C144.2 C154.2 C158.2 C163.2 C205.1 FR10.2 R177.1 R198.2 R203.2 R205.2 R206.2 R246.2 R256.2 R304.2 R352.1 U50.K9 U68.2 U68.3 U68.8 U68.9 U68.14 U68.15 U69.3 U69.4 U71.12 U71.27 U72.4 U73.4 U78.4 U92.4 U97.3 W3.1 | length 1634.5
  Top Layer w10: U50.K9@98.43,-59.06 v3(118.11,-78.74) ; v3(638.78,-149.12) U68.9@638.78,-109.25 ; v3(638.78,67.17) U68.8@638.78,109.25 ; v3(766.73,-196.85) C58.1@766.73,-177.17 U68.14@766.73,-109.25 U68.15@792.32,-109.25 ; C59.1@766.73,162.5 U68.3@766.73,109.25 U68.2@792.32,109.25 ; v2(947.83,71.77) U71.12@947.83,115.16 ; v2(1118.75,-1387.5) R198.2@1154.04,-1387.5 ; v2(1118.75,-1073.75) 1151.02,-1073.75 cw(c1151.02,-1078.02) R203.2@1154.04,-1075 ; v2(1203.74,-157.48) U71.27@1203.74,-115.16
  Top Layer w15: C142.2@1205.66,962.5 1246.6,1003.44 ccw(c1175.89,1074.15) 1275.89,1074.15 v1(1275.89,1076.67) ; C143.2@1211.91,1412.5 1246.6,1447.19 ccw(c1175.89,1517.9) 1275.89,1517.9 v1(1275.89,1526.67) ; v1(2041.8,1000.89) 2068.17,1000.89 cw(c2068.17,912.51) C116.2@2130.66,975 ; C117.2@2181.84,1675 ccw(c2244.33,1737.49) 2244.33,1649.11 v1(2270.42,1649.11)
  Top Layer w20: v3(492.13,275.59) 512.25,295.71 ccw(c441.54,366.42) 541.54,366.42 R177.1@541.54,375 ; v3(737.5,625) C57.2@761.91,625 ; U69.3@881.99,375 U69.4@881.99,425
  Bottom Layer w10: W3.1@433.07,-48.87 v3(433.07,-39.37)
  Bottom Layer w15: U72.4@1275.89,1050.1 cw(c1275.89,1007.23) 1318.75,1007.23 R205.2@1318.75,988.09 ; U73.4@1275.89,1500.1 cw(c1275.89,1457.23) 1318.75,1457.23 R206.2@1318.75,1438.09 ; U92.4@2068.38,1000.89 cw(c2111.24,1000.89) 2111.24,1043.75 R256.2@2130.66,1043.75 ; R304.2@2187.5,1545.96 cw(c2201.16,1559.63) 2181.84,1559.63 R246.2@2181.84,1606.25 2200.98,1606.25 ccw(c2200.98,1649.11) U78.4@2243.85,1649.11
  Bottom Layer w20: R352.1@877.5,408.46 885.08,408.46 ccw(c885.08,464.92) v3(925,425) ; v2(947.83,71.77) cw(c912.43,36.37) 962.5,36.37 C144.2@962.5,25.59
  other v3: 452.76,98.43 492.13,98.43 766.26,145 452.76,177.17 452.76,275.59
XADCVCC: C154.1 C158.1 C205.2 FR9.2 U50.K10 U97.1 | length 27.8
  Top Layer w10: U50.K10@59.06,-59.06 v3(78.74,-78.74)
  other v3: 570.87,78.74 570.87,177.17 570.87,275.59
pads on no net: J2.MH1 J2.MH2 P2.A19 P2.A32 P2.B12 P2.B17 P2.B30 P3.12 P3.14 S1.2 S1.4 U1.8 U34A.28 U34A.35 U34A.46 U34A.48 U34B.28 U34B.35 U34B.46 U34B.48 U34C.28 U34C.35 U34C.46 U34C.48 U34D.28 U34D.35 U34D.46 U34D.48 U34E.28 U34E.35 U34E.46 U34E.48 U34F.28 U34F.35 U34F.46 U34F.48 U34G.28 U34G.35 U34G.46 U34G.48 U34H.28 U34H.35 U34H.46 U34H.48 U43.4 U43.5 U43.6 U43.11 U43.12 U43.13 U43.14 U45.2 U45.3 U45.4 U45.13 U45.14 U45.15 U46.1 U46.4 U47.1 U48.1 U48.4 U50.A1 U50.AA5 U50.AA10 U50.AA18 U50.AA19 U50.AB3 U50.AB10 U50.AB11 U50.AB18 U50.B1 U50.B2 U50.C2 U50.D2 U50.D15 U50.D19 U50.E2 U50.E3 U50.E10 U50.E17 U50.E18 U50.E19 U50.F3 U50.F4 U50.F10 U50.F13 U50.F14 U50.F15 U50.F16 U50.F18 U50.F19 U50.F20 U50.G2 U50.G3 U50.G13 U50.G15 U50.G17 U50.G18 U50.G20 U50.G21 U50.G22 U50.H2 U50.H3 U50.H13 U50.H14 U50.J2 U50.J4 U50.J6 U50.J14 U50.K2 U50.K3 U50.K4 U50.K6 U50.K13 U50.K14 U50.K16 U50.K17 U50.L3 U50.L4 U50.L5 U50.L6 U50.L13 U50.L14 U50.L15 U50.L16 U50.L19 U50.M2 U50.M3 U50.M5 U50.M6 U50.M13 U50.M15 U50.M16 U50.N2 U50.N3 U50.N4 U50.N5 U50.N13 U50.N14 U50.N15 U50.N17 U50.P1 U50.P2 U50.P4 U50.P5 U50.P6 U50.P14 U50.P15 U50.P16 U50.P17 U50.P19 U50.P20 U50.R14 U50.R16 U50.R17 U50.R18 U50.R19 U50.T3 U50.T14 U50.T15 U50.T16 U50.T18 U50.T20 U50.T21 U50.U6 U50.U7 U50.U15 U50.U16 U50.U17 U50.U18 U50.U20 U50.V5 U50.V7 U50.V8 U50.V9 U50.V13 U50.V15 U50.V17 U50.V18 U50.V19 U50.V20 U50.W1 U50.W5 U50.W6 U50.W7 U50.W9 U50.W11 U50.W14 U50.W15 U50.W17 U50.W19 U50.Y1 U50.Y4 U50.Y6 U50.Y7 U50.Y8 U50.Y9 U50.Y12 U50.Y18 U50.Y19 U52.1 U52.4 U54.6 U54.8 U58.6 U58.8 U63.1 U63.3 U63.5 U63.7 U63.8 U66.1 U66.3 U66.5 U66.7 U66.8 U70.1 U71.2 U71.3 U71.13 U79.4 U79.7 U81.5 U82.3 U83.3 U84.3 U85.3 U86.3 U86.5 U87.3 U88.3 U88.5 U89.3 U90.3 U95.4 U95.9 U95.14 U96.4 U96.9 U96.14

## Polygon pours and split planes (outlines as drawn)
GND on Bottom Layer "GND_L12_P651" (solid, remove dead copper, pour order 651): -2025,-1781.25 -2025,-1931.25 -787.5,-1931.25 -637.5,-1781.25 1587.5,-1781.25 1587.5,775 1175,775 1175,1862.5 -2025,1862.5 -2025,1857.5
AGND on Bottom Layer "AGND_L12_P587" (solid, remove dead copper, pour order 587): -3587.5,1862.5 -2037.5,1862.5 -2037.5,-1931.25 -3587.5,-1931.25
XADCGND on Bottom Layer "XADCGND_L12_P584" (solid, pour order 584): 413.39,66.93 523.62,66.93 523.62,145.67 503.94,165.35 503.94,354.33 413.39,354.33
AGND on Bottom Layer "NONET_L-01_P-001" (solid, pour order 636): 1600,-531.25 2531.25,-531.25 2531.25,775 1600,775
AGND on Bottom Layer "NONET_L-01_P-001" (solid, remove dead copper, pour order 642): 1600,-1781.25 2531.25,-1781.25 2531.25,-893.75 1600,-893.75
GND on Bottom Layer "NONET_L-01_P-001" (solid, remove dead copper, pour order 638): 1187.5,1862.5 1187.5,800 2737.5,800 2737.5,1218.75 2350,1218.75 2350,1862.5
EXT12V on Bottom Layer "EXT12V_L12_P649" (solid, pour order 649): 2362.5,1533.56 2412.5,1533.56 2412.5,1428.25 2362.5,1428.25
12V on Bottom Layer "12V_L12_P648" (solid, pour order 648): 2362.5,1646.5 2412.5,1646.5 2412.5,1541.44 2362.5,1541.44
GND on Bottom Layer "NONET_L-01_P-001" (solid, remove dead copper, pour order 637): 2556.25,-1781.25 3256.25,-1781.25 3262.5,-1775 3262.5,775 2556.25,775
VCC on Bottom Layer "VCC_L12_P618" (solid, pour order 618): -50,-1050 -50,-920 275,-920 275,-1050
XADCVCC on Bottom Layer "XADCVCC_L12_P586" (solid, pour order 586): 519.69,354.33 519.69,157.48 531.5,145.67 531.5,19.69 570.87,19.69 570.87,59.06 594.49,82.68 594.49,354.33
AGND on Top Layer "AGND_L01_P585" (solid, remove dead copper, pour order 585): -3587.5,1867.5 -1362.5,1867.5 -1362.5,-1937.5 -3587.5,-1937.5
AGND on Top Layer "NONET_L-01_P-001" (solid, pour order 635): 2531.25,-1781.25 1600,-1781.25 1600,775 2531.25,775
NetC79_2 on Top Layer "NETC79_2_L01_P610" (solid, pour order 610): 2137.23,1535.47 2137.23,1362.97 1987.23,1362.97 1987.23,1535.47
12V on Top Layer "12V_L01_P647" (solid, pour order 647): 2362.5,1646.38 2412.5,1646.38 2412.5,1541.44 2362.5,1541.44
NetD4_2 on Top Layer "NETD4_2_L01_P646" (solid, pour order 646): 2362.5,1533.56 2412.5,1533.56 2412.5,1427.02 2362.5,1427.02
NetC88_2 on Top Layer "NETC88_2_L01_P594" (solid, pour order 594): 2960,651.25 2718.75,651.25 2718.75,775 2960,775
SW+16V on Top Layer "SW+16V_L01_P574" (solid, pour order 574): 2806.25,-665 2806.25,-975 2581.25,-975 2581.25,-1050.1 2556.25,-1049.92 2556.25,-800 2725,-800 2725,-665
NetC89_2 on Top Layer "NETC89_2_L01_P561" (solid, pour order 561): 2556.25,-226.25 2725,-226.25 2725,-359.89 2806.25,-359.89 2806.25,-37.5 2581.25,-37.5 2581.25,37.5 2556.25,37.5 2556.25,-37.5
NetC90_1 on Top Layer "NETC90_1_L01_P575" (solid, pour order 575): 2556.25,500 2718.75,500 2718.75,630 2806.25,630 2806.25,312.5 2581.25,312.5 2581.25,237.5 2556.25,237.5
NetC98_2 on Top Layer "NETC98_2_L01_P555" (solid, pour order 555): 2881.25,-1256.25 2881.25,-1325 2881.25,-1537.5 2958.75,-1537.5 2958.75,-1306.25 3056.25,-1306.25 3056.25,-1256.25 3033.75,-1256.25 3033.75,-1287.5 2903.75,-1287.5 2903.75,-1256.25
GND on Top Layer "GND_L01_P583" (solid, pour order 583): 2556.25,-781.42 2706.25,-781.42 2706.25,-525 2556.25,-525
GND on Top Layer "GND_L01_P639" (solid, pour order 639): 2706.25,-500 2706.25,-243.75 2556.25,-243.75 2556.25,-500
NetC99_1 on Top Layer "NETC99_1_L01_P559" (solid, pour order 559): 2818.75,-256.25 2818.75,-37.5 2960,-37.5 2960,-256.25
NetC88_2 on Top Layer "NETC88_2_L01_P563" (solid, pour order 563): 2960,-500 2725,-500 2725,-375 2960,-375
SW-16V on Top Layer "SW-16V_L01_P560" (solid, pour order 560): 2556.25,-1781.25 2958.75,-1781.25 2958.75,-1662.5 2800,-1662.5 2800,-1575 2556.25,-1575
GND on Top Layer "GND_L01_P640" (solid, pour order 640): 2706.27,518.75 2706.27,775 2556.27,775 2556.27,518.75
GND on Top Layer "GND_L01_P591" (solid, pour order 591): 3075,-500 2977.5,-500 2977.5,-375 3075,-375
GND on Top Layer "GND_L01_P590" (solid, pour order 590): 2687.5,-1550 2800,-1550 2800,-1325 2687.5,-1325
NetC97_2 on Top Layer "NETC97_2_L01_P577" (solid, pour order 577): 2881.25,-1043.75 2903.75,-1043.75 2903.75,-1012.5 3033.75,-1012.5 3033.75,-1043.75 3056.25,-1043.75 3056.25,-768.75 2977.5,-768.75 2977.5,-993.75 2881.25,-993.75
NetC87_1 on Top Layer "NETC87_1_L01_P592" (solid, pour order 592): 2725,-525 2960,-525 2960,-650 2725,-650
NetC97_1 on Top Layer "NETC97_1_L01_P579" (solid, pour order 579): 2818.75,-975 2818.75,-768.75 2960,-768.75 2960,-975
NetC98_1 on Top Layer "NETC98_1_L01_P558" (solid, pour order 558): 2978.75,-1537.5 2978.75,-1325 3118.75,-1325 3118.75,-1537.5
GND on Top Layer "GND_L01_P564" (solid, pour order 564): 3141.25,-1587.5 3141.25,-1325 3256.25,-1325 3256.25,-1587.5
SW-16V on Top Layer "SW-16V_L01_P581" (solid, pour order 581): 2556.25,-1781.25 2556.25,-1243.75 2581.25,-1243.75 2581.25,-1325 2668.75,-1325 2668.75,-1781.25
NetC87_1 on Top Layer "NETC87_1_L01_P562" (solid, pour order 562): 2978.75,-1662.5 3141.25,-1662.5 3141.25,-1612.5 3256.25,-1612.5 3256.25,-1781.25 2978.75,-1781.25
GND on Top Layer "GND_L01_P593" (solid, pour order 593): 2977.5,-525 3075,-525 3075,-650 2977.5,-650
NetC78_2 on Top Layer "NETC78_2_L01_P609" (solid, pour order 609): 1987.5,1165 1987.5,1337.5 2137.5,1337.5 2137.5,1165
NetC100_2 on Top Layer "NETC100_2_L01_P578" (solid, pour order 578): 2881.25,243.75 2903.75,243.75 2903.75,275 3033.75,275 3033.75,243.75 3056.25,243.75 3056.25,531.25 2977.5,531.25 2977.5,293.75 2881.25,293.75
NetC99_2 on Top Layer "NETC99_2_L01_P556" (solid, pour order 556): 2881.25,31.25 2881.25,-18.75 2977.5,-18.75 2977.5,-256.25 3056.25,-256.25 3056.25,31.25 3033.75,31.25 3033.75,0 2903.75,0 2903.75,31.25
NetC100_1 on Top Layer "NETC100_1_L01_P580" (solid, pour order 580): 2818.75,312.5 2818.75,531.25 2960,531.25 2960,312.5
GND on Top Layer "GND_L01_P596" (solid, pour order 596): 3131.25,651.25 2977.5,651.25 2977.5,775 3131.25,775
VCC1V8 on Int6 (SB) "VCC1V8_L07_P650" (solid, pour order 650): -1268.75,-1790 -1268.75,1881.35 -1965,1881.35 -1965,-1790
AVTT on Int6 (SB) "AVTT_L07_P623" (solid, pour order 623): 0,-356.25 81.18,-356.25 118.55,-314.96 156.21,-314.96 185,-343.75 412.65,-343.75 787.65,-718.75 2056.25,-718.75 2056.25,-887.5 509.74,-887.5 0,-377.76
SENS_120f_N on Int6 (SB) "SENS_120F_N_L07_P611" (solid, pour order 611): 1962.5,1162.5 1962.5,1562.5 1487.5,1562.5 1487.5,1162.5
AVCC on Int6 (SB) "AVCC_L07_P624" (solid, pour order 624): 55.77,-337.93 98.43,-295.28 177.17,-295.28 213.14,-331.25 418.75,-331.25 793.75,-706.25 2056.25,-706.25 2056.25,-537.5 990,-537.5 619.82,-167.32 39.37,-167.32 0,-206.69 0,-337.93
XADCVCC on Int6 (SB) "XADCVCC_L07_P622" (solid, pour order 622): 39.37,-48.75 39.37,-147.64 483.61,-147.64 610.24,-21.01 610.24,295.28 590.55,314.96 551.18,314.96 531.5,295.28 531.5,39.37 443.38,-48.75
SW+2V5 on Int6 (SB) "SW+2V5_L07_P643" (solid, pour order 643): 2300,-837.5 2300,106.25 2368.75,106.25 2368.75,-837.5
VREF-PH on Int6 (SB) "VREF-PH_L07_P621" (solid, pour order 621): 481.25,-1800 108.75,-1800 12.5,-1713.38 12.5,-1468.75 431.25,-1050 562.5,-1050 562.5,-1718.75
VREF-PH2 on Int5 (ST) "VREF-PH2_L06_P633" (solid, pour order 633): 75,1843.75 593.75,1843.75 593.75,1175 462.5,1043.75 206.25,1043.75 75,1175
VREG on Int5 (ST) "VREG_L06_P620" (solid, pour order 620): 1975,1037.5 1975,1850 1487.5,1850 1487.5,1037.5
GND on Int1 (GND) (split plane): 105 vertices, not listed, extent -3579.9,-2290.24 3252.41,1861.25
EXTGND on Int1 (GND) (split plane): 133 vertices, not listed, extent -1843.54,-2467.4 3387.78,1861.25
VCOMF on Int2 (AVDD) (split plane): -1985.09,-827.41 -2852.41,-827.41 -2852.41,-397.59 -1985.09,-397.59
VCOME on Int2 (AVDD) (split plane): -1985.09,-377.41 -2852.41,-377.41 -2852.41,52.41 -1985.09,52.41
VCOMG on Int2 (AVDD) (split plane): -1985.09,-1277.41 -2852.41,-1277.41 -2852.41,-847.59 -1985.09,-847.59
AGND on Int2 (AVDD) (split plane): 57 vertices, not listed, extent -3579.9,-2290.24 -1916.17,1861.25
VCOMB on Int2 (AVDD) (split plane): -1985.09,972.59 -2852.41,972.59 -2852.41,1402.41 -1985.09,1402.41
VCOMA on Int2 (AVDD) (split plane): -1985.09,1422.59 -2852.41,1422.59 -2852.41,1861.25 -1985.09,1861.25
VCOMD on Int2 (AVDD) (split plane): -1985.09,72.59 -2852.41,72.59 -2852.41,502.41 -1985.09,502.41
VCOMC on Int2 (AVDD) (split plane): -1985.09,522.59 -2852.41,522.59 -2852.41,952.41 -1985.09,952.41
BUS12V on Int2 (AVDD) (split plane): 81 vertices, not listed, extent -1843.53,-2467.4 944.64,-1585.09
DVDD5V0 on Int2 (AVDD) (split plane): 102 vertices, not listed, extent -1964.91,-1964.91 1989.91,1861.25
VCC1V8 on Int2 (AVDD) (split plane): 62 vertices, not listed, extent -1514.91,-1789.91 2714.91,1861.25
NetD4_2 on Int2 (AVDD) (split plane): 49 vertices, not listed, extent 964.81,-1965.43 3387.78,1861.25
VCOMH on Int2 (AVDD) (split plane): -1985.09,-1789.91 -2845.82,-1789.91 -2852.41,-1783.32 -2852.41,-1297.59 -1985.09,-1297.59
VCC2 on Int2 (AVDD) (split plane): 18 vertices, not listed, extent 630.16,-108.02 1239.91,1200.54
NetC87_1 on Int2 (AVDD) (split plane): 3252.41,-1770.82 3233.32,-1789.91 2460.09,-1789.91 2460.09,-522.59 3252.41,-522.59
NetC88_2 on Int2 (AVDD) (split plane): 18 vertices, not listed, extent 2460.09,-502.41 3252.41,1227.41
EXTGND on Int3 (DVDD) (split plane): 130 vertices, not listed, extent -1843.53,-2467.4 3387.78,1861.25
AGND on Int3 (DVDD) (split plane): 60 vertices, not listed, extent -3579.9,-2290.24 -1939.81,1861.25
AVDD5V0 on Int3 (DVDD) (split plane): 72 vertices, not listed, extent -2996.16,-1964.91 2439.91,1861.25
VCC2V5 on Int3 (DVDD) (split plane): 43 vertices, not listed, extent -1514.91,-1464.91 2714.91,1861.25
12VA on Int3 (DVDD) (split plane): 22 vertices, not listed, extent 2460.09,-1789.91 3252.41,1227.41
AVCC1V8 on Int3 (DVDD) (split plane): 41 vertices, not listed, extent 521.9,453 1577.41,1427.41
VCC1V0 on Int3 (DVDD) (split plane): 78 vertices, not listed, extent -9.6,-167.08 2264.91,1577.41
AGND on Int4 (GND) (split plane): 59 vertices, not listed, extent -3579.9,-2290.24 -1939.81,1861.25
GND on Int4 (GND) (split plane): 153 vertices, not listed, extent -2089.91,-1964.91 3252.41,1861.25
EXTGND on Int4 (GND) (split plane): 91 vertices, not listed, extent -1843.53,-2467.4 3387.78,764.91
XADCGND on Int4 (GND) (split plane): 82 vertices, not listed, extent 110.09,-1464.91 2364.91,1861.25
12V on Int4 (GND) (split plane): 41 vertices, not listed, extent 2385.09,785.09 3387.78,1861.25
EXTGND on Int8 (AGND) (split plane): 92 vertices, not listed, extent -1843.53,-2467.4 3387.78,764.91
AGND on Int8 (AGND) (split plane): 89 vertices, not listed, extent -3579.9,-2290.24 2439.91,1861.25
GND on Int8 (AGND) (split plane): 62 vertices, not listed, extent -1164.91,-1789.91 3252.41,1861.25
12V on Int8 (AGND) (split plane): 30 vertices, not listed, extent 2385.09,785.09 3387.78,1861.25
+15V on Int7 (AVCC) (split plane): 84 vertices, not listed, extent -3579.9,-2290.24 1583.66,1861.25
DVDD1V8 on Int7 (AVCC) (split plane): 52 vertices, not listed, extent -2089.91,-1789.91 2439.91,1861.25
EXTGND on Int7 (AVCC) (split plane): 118 vertices, not listed, extent -1843.53,-2467.4 3387.78,1861.25
VCC on Int7 (AVCC) (split plane): 29 vertices, not listed, extent -1164.91,-1352.41 2714.91,1861.25
GND on Int7 (AVCC) (split plane): 21 vertices, not listed, extent 2460.09,-1789.91 3252.41,1227.41
BUS12V on Int9 (VCCA) (split plane): 74 vertices, not listed, extent -1843.53,-2467.4 944.64,-1585.09
-15V on Int9 (VCCA) (split plane): 85 vertices, not listed, extent -3579.9,-2290.24 1583.66,1861.25
AVDD1V8 on Int9 (VCCA) (split plane): 55 vertices, not listed, extent -2089.92,-1789.91 2439.91,1861.25
NetD4_2 on Int9 (VCCA) (split plane): 54 vertices, not listed, extent 964.81,-1965.43 3387.78,1861.25
VCC2V5 on Int9 (VCCA) (split plane): 33 vertices, not listed, extent -1164.91,-1352.41 2714.91,1861.25
GND on Int9 (VCCA) (split plane): 19 vertices, not listed, extent 2460.09,-1789.91 3252.41,1227.41
GND on Int10 (GND) (split plane): 92 vertices, not listed, extent -3579.9,-2290.24 3252.41,1861.25
EXTGND on Int10 (GND) (split plane): 118 vertices, not listed, extent -1843.53,-2467.4 3387.78,1861.25

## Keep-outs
Top Layer:
  rectangle: -477.5,-1985.53 3407.87,-1946.16
  rectangle: -3600,1042.5 -3100,1867.5
  region: -3600,-2312.32 -3009.45,-2312.32 ccw(c-3009.45,-2310.33) -3007.47,-2310.33 -3007.47,-1987.51 -2288.99,-1987.51 -2288.99,-2174.51 ccw(c-2287.01,-2174.51) -2287.01,-2176.49 -1972.05,-2176.49 ccw(c-1972.05,-2174.51) -1970.06,-2174.51 -1970.06,-2057.38 cw(c-1900.2,-2057.38) -1830.33,-2057.38 ccw(c-1828.35,-2057.38) -1826.36,-2057.38 -1826.36,-1946.16 ccw(c-1828.35,-1946.16) -1828.35,-1944.18 -3600,-1944.18 ccw(c-3600,-1946.16) -3601.98,-1946.16 -3601.98,-2310.33 ccw(c-3600,-2310.33)
Bottom Layer:
  rectangle: -477.5,-1985.53 3407.5,-1946.16
  rectangle: -3600,1042.5 -3100,1867.5
  region: -3600,-2312.32 -3009.45,-2312.32 ccw(c-3009.45,-2310.33) -3007.47,-2310.33 -3007.47,-1987.51 -2288.99,-1987.51 -2288.99,-2174.51 ccw(c-2287.01,-2174.51) -2287.01,-2176.49 -1972.05,-2176.49 ccw(c-1972.05,-2174.51) -1970.06,-2174.51 -1970.06,-2057.38 cw(c-1900.2,-2057.38) -1830.33,-2057.38 ccw(c-1828.35,-2057.38) -1826.36,-2057.38 -1826.36,-1946.16 ccw(c-1828.35,-1946.16) -1828.35,-1944.18 -3600,-1944.18 ccw(c-3600,-1946.16) -3601.98,-1946.16 -3601.98,-2310.33 ccw(c-3600,-2310.33)
Top Solder:
  rectangle: -2287.01,-2310.33 -1972.05,-2174.51
Bottom Solder:
  rectangle: -2287.01,-2310.33 -1972.05,-2174.51
KeepOutLayer:
  rectangle: -2287.01,-2310.33 -1972.05,-2174.51

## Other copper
Top Layer:
  rectangle net GND: 2556.25,-537.5 2581.25,-487.5
  rectangle net AGND: 2506.25,-537.5 2531.25,-487.5
  region net AGND: -3257.28,887.5 -3600,887.5 -3600,651.28 -3367.65,651.28 -3352.3,653.3 -3337.35,657.31 -3323.04,663.23 -3309.63,670.97 -3297.35,680.4 -3286.4,691.35 -3276.98,703.63 -3269.24,717.04 -3263.31,731.34 -3259.3,746.3 -3257.28,761.65 -3257.28,769.39
  region net AGND: -3257.28,-1762.5 -3600,-1762.5 -3600,-1526.28 -3375.39,-1526.28 -3367.65,-1526.28 -3352.3,-1528.3 -3337.35,-1532.31 -3323.04,-1538.23 -3309.63,-1545.97 -3297.35,-1555.4 -3286.4,-1566.35 -3276.98,-1578.63 -3269.24,-1592.04 -3263.31,-1606.34 -3259.3,-1621.3 -3257.28,-1636.65 -3257.28,-1644.39
Int8 (AGND) (plane layer: these items are gaps in the copper):
  lines w20: -1925,-1975 -800,-1975 -625,-1800 621.06,-1800 846.06,-1575 1047.24,-1575 1052.67,-1580.43 1272.24,-1800 3237.5,-1800 3262.5,-1775 3262.5,-1700 ; -1175,1882.5 -1175,800 -1175,-1362.5 -537.5,-1362.5 437.5,-1362.5 904.23,-895.77 1293.75,-506.25 1293.75,273.75 1122.5,445 1122.5,531.25 1372.5,781.25 2450,781.25 2450,-1800 ; 2375,1882.5 2375,1237.5 2725,1237.5 2725,781.25 2970,781.25 2970,1237.5 3175,1237.5 3175,862.5 3262.5,775 ; 3417.5,775 3262.5,775 ; 3262.5,-1700 3262.5,775 ; 3262.5,-1700 3262.5,-1700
